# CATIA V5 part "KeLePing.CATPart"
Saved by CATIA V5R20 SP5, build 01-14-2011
Part number: keleping
Material "Cloudy Sky"
Material "Steel": density 7860 kg/m3, Young's modulus 2e+11 Pa, Poisson ratio 0.266, thermal expansion 1.17e-05 1/K
Bounding box of the stored display mesh (mm): x -25 to 806.467, y -25.2 to 25, z -50 to 489.591
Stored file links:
  E:\180212313\180212313林恺昇\KeLePing.CATPart
  C:\Program Files\Dassault Systemes\B20\intel_a\startup\materials\Catalog.CATMaterial
  C:\Program Files\Dassault Systemes\B20\intel_a\startup\materials\DS_star.jpg
  C:\Program Files\Dassault Systemes\B20\intel_a\startup\materials\eroded_metal_2.jpg
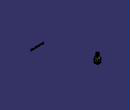
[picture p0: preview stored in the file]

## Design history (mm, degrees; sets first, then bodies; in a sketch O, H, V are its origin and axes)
Set1
  Sketch1 on xy-plane, origin (0, 0, 0), H (1, 0, 0), V (0, 1, 0)
    line L1 (25, 25) -> (25, -25)
    line L2 (25, -25) -> (-25, -25)
    line L3 (-25, -25) -> (-25, 25)
    line L4 (-25, 25) -> (25, 25)
    length L1 = 50
    length L2 = 50
    vertical: L1 V, L3 V
    horizontal: L2 H, L4 H
    equidistance: L1 L3 O, L2 L4 O
  Sketch2 on face of Pad1 from Sketch1.L1, origin (25, 0, 0), H (0, 1, 0), V (0, 0, 1)
    spline S1 through (-29.6806, -39.5643) (-9.6806, -29.5643) (10.3194, -39.5643) (30.3194, -29.5643)
  Extrude1: Element1 Sketch2, Lim1 52, Lim2 4
  MultiSel1: CommonCtxFeats ({extract ExtractElem face of Pad1 from Sketch1.L3}; {extract ExtractElem face of Fillet1}; {extract ExtractElem face of Pad1 from Sketch1.L4}; {extract ExtractElem face of Fillet1}; {extract ExtractElem face of Pad1 from Sketch1.L1}; {extract ExtractElem face of Fillet1}; {extract ExtractElem face of Pad1 from Sketch1.L2}; {extract ExtractElem face of Fillet1})
  Sketch3 on yz-plane, origin (0, 0, 0), H (0, 1, 0), V (0, 0, 1)
    spline S1 through (-30, -30) (-10, -20) (10, -30) (30, -20)
  Extrude2: Element1 Sketch3, Lim1 52, Lim2 52
  MultiSel2: CommonCtxFeats ({extract ExtractElem face of Pad1 from Sketch1.L2}; {extract ExtractElem face of Fillet1}; {extract ExtractElem face of Pad1 from Sketch1.L3}; {extract ExtractElem face of Fillet1}; {extract ExtractElem face of Pad1 from Sketch1.L4}; {extract ExtractElem face of Fillet1}; {extract ExtractElem face of Pad1 from Sketch1.L1}; {extract ExtractElem face of Fillet1})
  Join1: Elements ({intersect ToIntersect1 {extract ExtractElem face of Pad1 from Sketch1.L3}, ToIntersect2 Extrude1}; {intersect ToIntersect1 {extract ExtractElem face of Fillet1}, ToIntersect2 Extrude1}; {intersect ToIntersect1 {extract ExtractElem face of Pad1 from Sketch1.L4}, ToIntersect2 Extrude1}; {intersect ToIntersect1 {extract ExtractElem face of Fillet1}, ToIntersect2 Extrude1}; {intersect ToIntersect1 {extract ExtractElem face of Pad1 from Sketch1.L1}, ToIntersect2 Extrude1}; {intersect ToIntersect1 {extract ExtractElem face of Fillet1}, ToIntersect2 Extrude1}; {intersect ToIntersect1 {extract ExtractElem face of Pad1 from Sketch1.L2}, ToIntersect2 Extrude1}; {intersect ToIntersect1 {extract ExtractElem face of Fillet1}, ToIntersect2 Extrude1})
  Join2: Elements ({intersect ToIntersect1 {extract ExtractElem face of Pad1 from Sketch1.L2}, ToIntersect2 Extrude2}; {intersect ToIntersect1 {extract ExtractElem face of Fillet1}, ToIntersect2 Extrude2}; {intersect ToIntersect1 {extract ExtractElem face of Pad1 from Sketch1.L3}, ToIntersect2 Extrude2}; {intersect ToIntersect1 {extract ExtractElem face of Fillet1}, ToIntersect2 Extrude2}; {intersect ToIntersect1 {extract ExtractElem face of Pad1 from Sketch1.L4}, ToIntersect2 Extrude2}; {intersect ToIntersect1 {extract ExtractElem face of Fillet1}, ToIntersect2 Extrude2}; {intersect ToIntersect1 {extract ExtractElem face of Pad1 from Sketch1.L1}, ToIntersect2 Extrude2}; {intersect ToIntersect1 {extract ExtractElem face of Fillet1}, ToIntersect2 Extrude2})
  Plane1: type Normal, Curve Join1, RefPoint vertex [face of MultiSel1 | face of MultiSel1]
  Sketch4 on Plane1, origin (14.0113, 0, 0), H (0, 1, 0), V (0, 0, 1)
    circle A1 centre (25, -35.6132) radius 2
    point P1 (25, -35.6132)
    reference projected point E1 (25, -35.6132) from vertex [face of MultiSel1 | face of MultiSel1]
    radius A1 = 2
    coincidence: E1 P1
Body1 (main body), material "Steel"
  Pad1: profile Sketch1, direction (0, 0, -1), length 50
  Fillet1: on edge [face of Pad1 from Sketch1.L3 | face of Pad1 from Sketch1.L4]; edge [face of Pad1 from Sketch1.L2 | face of Pad1 from Sketch1.L3]; edge [face of Pad1 from Sketch1.L4 | face of Pad1 from Sketch1.L1]; edge [face of Pad1 from Sketch1.L1 | face of Pad1 from Sketch1.L2]
  Plane2: type Offset, RefPlane xy-plane, Offset 40
  Sketch5 on Plane2, origin (0, 0, 40), H (1, 0, 0), V (0, 1, 0)
    circle A1 centre (0, 0) radius 15
    radius A1 = 15
  Pad2: profile Sketch5, direction (0, 0, 1), length 20
  Fillet2: radius 8, on end face of Pad1
  Sketch6 on start face of Pad2, origin (0, 0, 40), H (1, 0, 0), V (0, -1, 0)
    point P1 (15, 0)
    distance P1 O = 15
    coincidence: P1 H
  Sketch7 on start face of Pad1, origin (0, 0, 0), H (1, 0, 0), V (0, 1, 0)
    point P1 (25, 0)
    distance P1 O = 25
  Loft1: solid, Sections ({boundary Boundary {extract ExtractElem start face of Pad2}}; {boundary Boundary {extract ExtractElem start face of Pad1}}), StartFace start face of Pad2, EndFace start face of Pad1
  Slot1: profile Sketch4, centre curve Join1
  Plane3: type Normal, Curve Join2, RefPoint vertex [face of MultiSel2 | face of MultiSel2]
  Sketch8 on Plane3, origin (12.0115, 0, 0), H (0, -1, 0), V (0, 0, 1)
    circle A1 centre (-25, -25.7582) radius 2
    point P1 (-25, -25.7582)
    reference projected point E1 (-25, -25.7582) from vertex [face of MultiSel2 | face of MultiSel2]
    radius A1 = 2
    coincidence: P1 E1
  Slot2: profile Sketch8, centre curve Join2
  Shell1: ExtOffset 0, Face end face of Pad2, IntOffset 1
  Plane4: type Offset, RefPlane Plane2, Offset 2
  Sketch9 on Plane4, origin (0, 0, 42), H (1, 0, 0), V (0, 1, 0)
    point P1 (15, 0)
    distance P1 O = 15
    coincidence: P1 H
  Helix1: Direction Z axis, RefPoint Sketch9, Pitch 3, Height 16, TaperAngle 0
  Point1: type OnCurve, Support Helix1, Length 5
  Line1: type PtDir, RefPoint Sketch9, Direction (1, 0, 0), Start 0, End 5
  Connect1: Curve1 Line1, Point1 vertex of Line1, Tension1 1, Curve2 Helix1, Point2 Point1, Tension2 1
  Point2: type OnCurve, Support Connect1, RefPoint vertex of Helix1, Length 6
  Line2: type PtDir, RefPoint vertex of Helix1, Direction (0, 1, 0), Start 0, End 5
  Connect2: Curve1 Line2, Point1 vertex of Line2, Tension1 1, Curve2 Connect1, Point2 Point2, Tension2 1
  Plane5: type Normal, Curve Connect2, RefPoint vertex of Connect1
  Sketch10 on Plane5, origin (10, 0, 0), H (0, -1, 0), V (0, 0, 1)
    circle A1 centre (0, 41.8348) radius 1
    point P1 (0, 41.8348)
    radius A1 = 1
    coincidence: P1 V
  Rib1: profile Sketch10, centre curve Connect2
  Body2
    Sketch11 on Plane2, origin (0, 0, 40), H (1, 0, 0), V (0, 1, 0)
      circle A1 centre (0, 0) radius 14
      radius A1 = 14
    Pad3: profile Sketch11, direction (0, 0, -1), length 40, mirrored extent
  Remove1: tool Body2
Body3, material "Cloudy Sky"
  Sketch12 on face of Pad1 from Sketch1.L2, origin (0, -25, 0), H (1, 0, 0), V (0, 0, 1)
    polyline C1
    polyline C2
    polyline C3
    polyline C4
    polyline C5
    polyline C6
    polyline C7
    polyline C8
    polyline C9
    polyline C10
    polyline C11
    polyline C12
    polyline C13
    point P1 (0, -33.1833)
    construction line L1 through (0, -33.1833) direction (1, 0)
    polyline C14
    polyline C15
    polyline C16
    polyline C17
    polyline C18
    polyline C19
    polyline C20
    polyline C21
    polyline C22
    polyline C23
    polyline C24
    polyline C25
    polyline C26
  Sketch13 on face of Pad1 from Sketch1.L2, origin (0, -25, 0), H (1, 0, 0), V (0, 0, 1)
  Pad4: profile Sketch12, direction (0, -1, 0), length 0.2, mirrored extent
